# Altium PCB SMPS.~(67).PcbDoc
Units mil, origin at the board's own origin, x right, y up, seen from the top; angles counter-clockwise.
Board outline 3937.01 x 3149.61 mil, 2 copper layers (Top Layer, Bottom Layer); 139 components, 61 nets, 425 pads, 69 vias.
Unrouted connection lines stored in the file: 114.
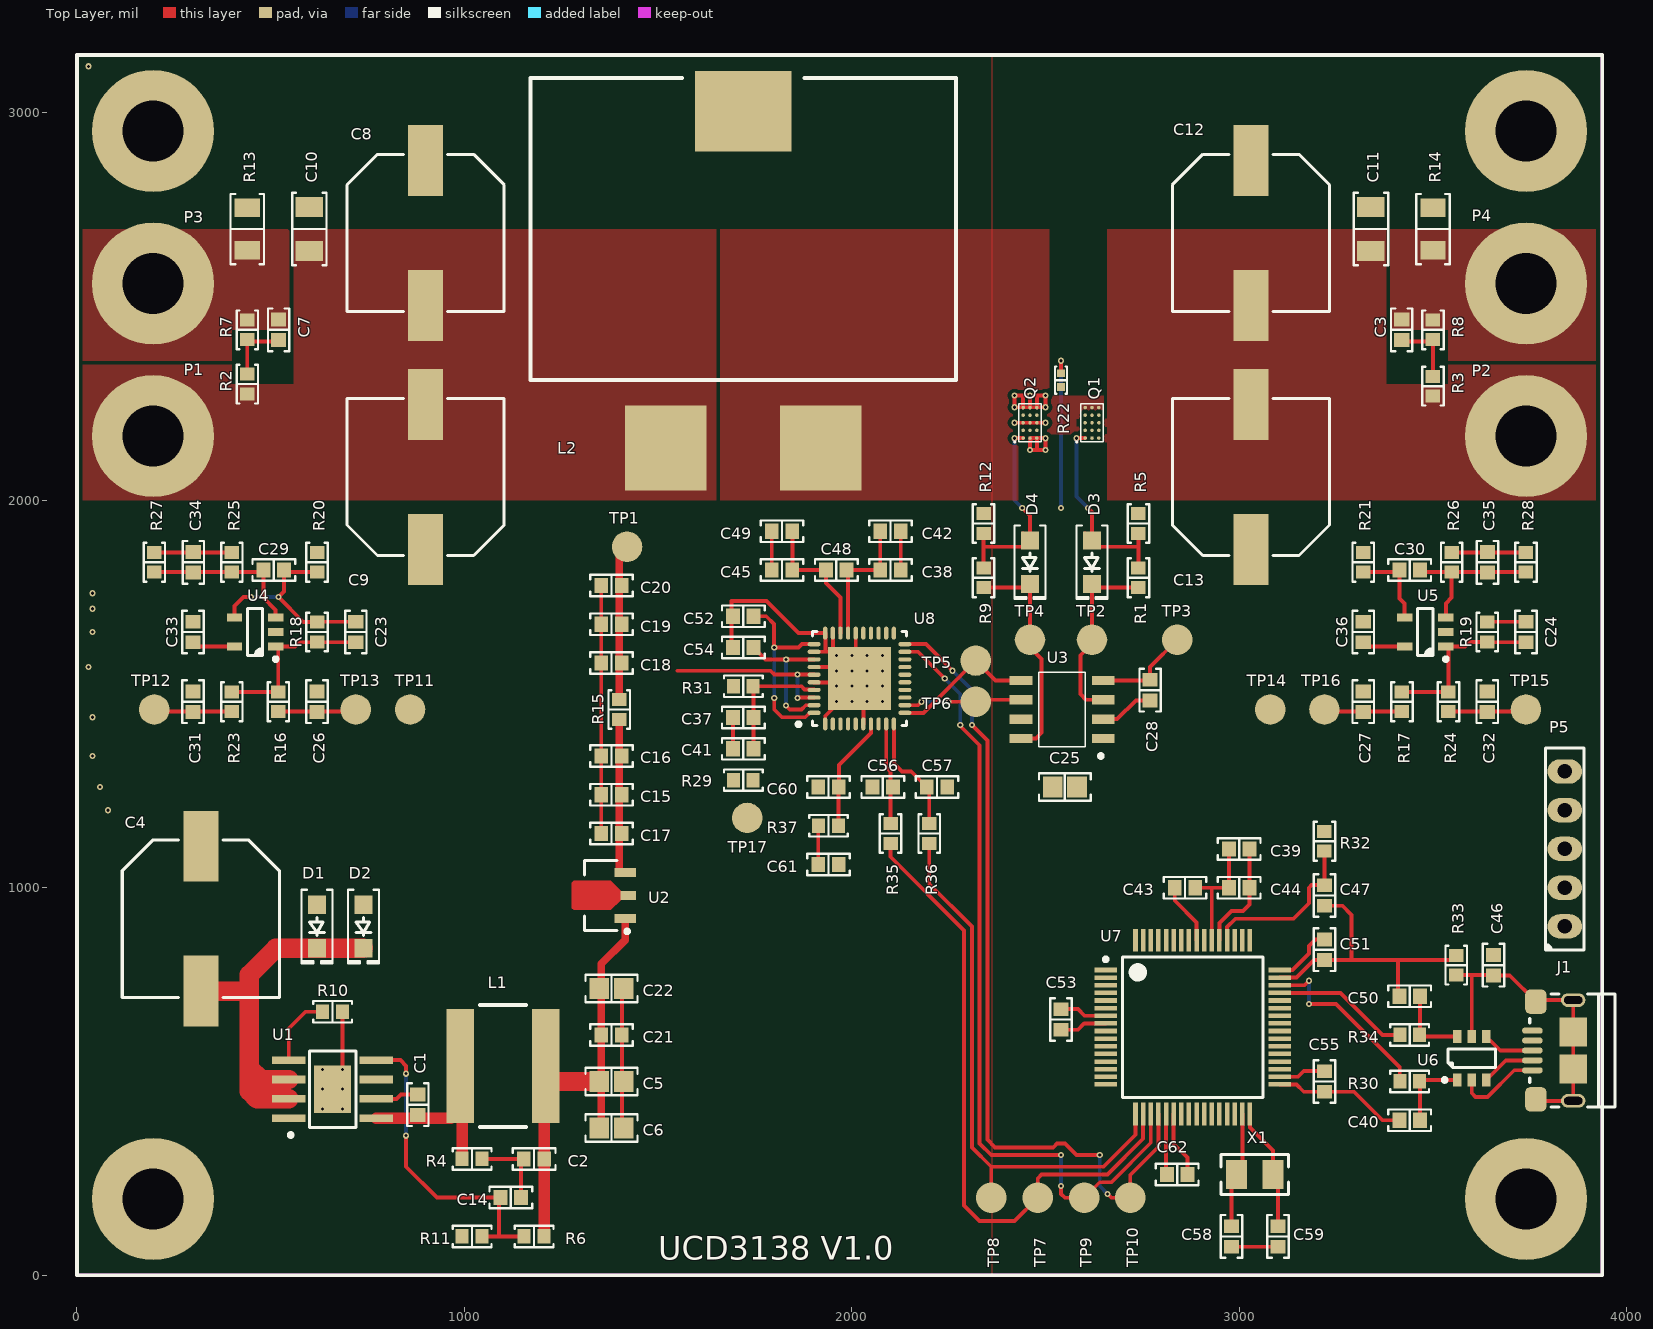
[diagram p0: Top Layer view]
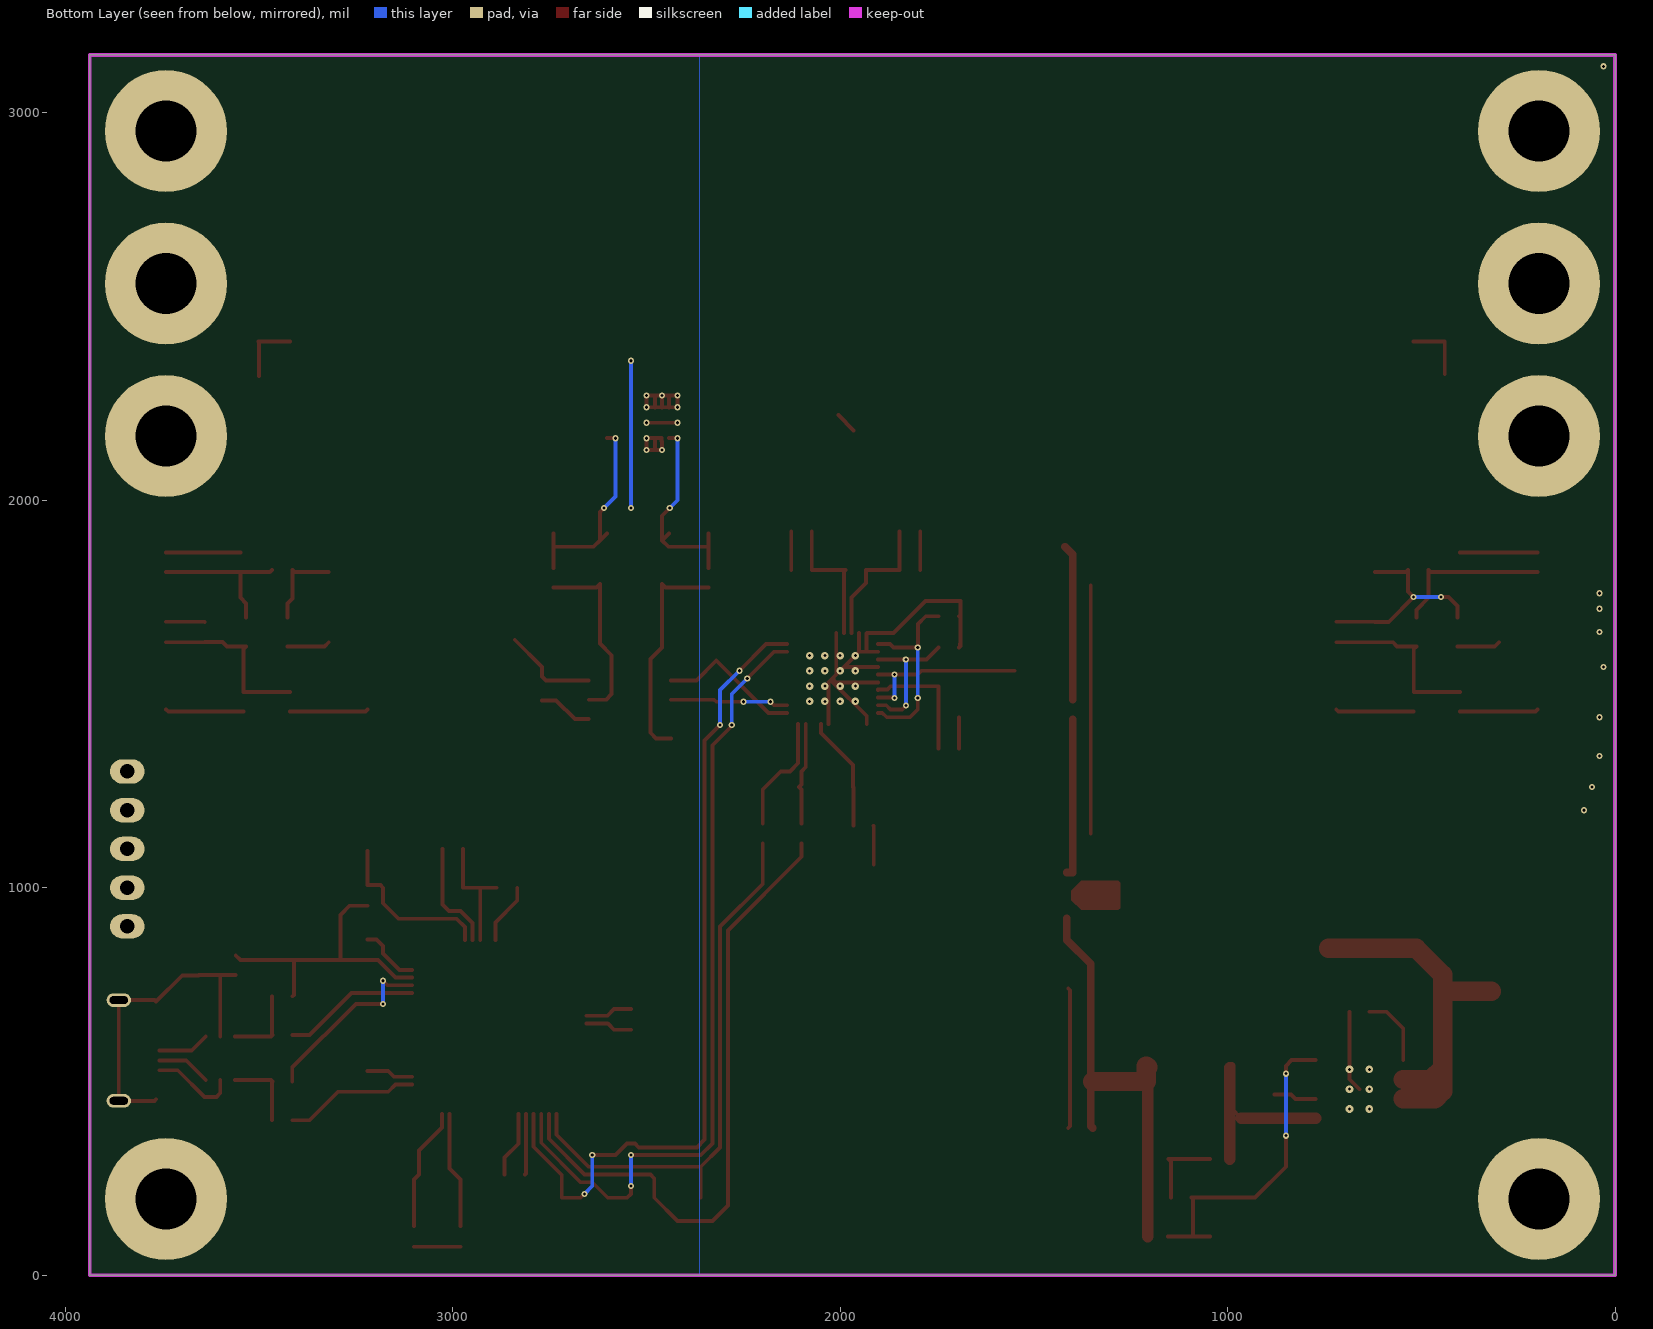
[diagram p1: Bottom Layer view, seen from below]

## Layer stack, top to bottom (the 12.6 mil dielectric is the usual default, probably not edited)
Top Solder: solder mask 0.4, Solder Resist, Dk 3.5
Top Layer: signal copper 1.4
Dielectric 1: dielectric 12.6, FR-4, Dk 4.8
Bottom Layer: signal copper 1.4
Bottom Solder: solder mask 0.4, Solder Resist, Dk 3.5

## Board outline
0,0 0,3149.61 3937.01,3149.61 3937.01,0

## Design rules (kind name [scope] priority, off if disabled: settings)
Clearance [All] p1: gap=10 ignorepadtopadclearanceinfootprint=FALSE except(0: Arc-Hole Track-Hole SMDPad-Hole THPad-Hole Via-Hole Fill-Hole Poly-Hole Region-Hole Text-Hole; 7: SMDPad-SMDPad; 8: Track-SMDPad; 9: Arc-Arc Arc-Track Arc-SMDPad Track-Track; 20: THPad-THPad)
ComponentClearance U1 [InComponent('U1')] p1: gap=20 collisioncheckmode=3 verticalgap=0 showdistances=TRUE
ComponentClearance [All] p2: gap=19.68 collisioncheckmode=3 verticalgap=3.94 showdistances=TRUE
Height [All] p1: minheight=0 maxheight=2000 prefheight=500
HoleSize [All] p1: absolutevalues=TRUE maxlimit=393.7 minlimit=7.87 maxpercent=80.000 minpercent=20.000
MinimumSolderMaskSliver [All] p1: minsoldermaskwidth=1
PlaneClearance [All] p1: clearance=10
PlaneConnect [All] p1: planeconnectstyle=Direct reliefexpansion=20 reliefentries=4 reliefconductorwidth=20 reliefairgap=20
PolygonConnect GND [InNet('GND')] p1: connectstyle=Direct reliefconductorwidth=10 reliefentries=4 polygonreliefangle="90 Angle" airgapwidth=10
PolygonConnect DirectConnect [All] p2: connectstyle=Direct reliefconductorwidth=10 reliefentries=4 polygonreliefangle="90 Angle" airgapwidth=10
RoutingVias [All] p1: holewidth=7.87 width=31.5 viastyle="Through Hole" minholewidth=7.87 minwidth=15.75 maxholewidth=15.75 maxwidth=31.5
SilkToSilkClearance [All] p1: silktosilkclearance=0
SolderMaskExpansion [All] p1: expansion=4
Width [All] p1: maxlimit=500 minlimit=10 preferedwidth=10
23 further rules are at their usual default settings.

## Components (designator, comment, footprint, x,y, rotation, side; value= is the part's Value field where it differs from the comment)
C1 "10nF" C0603 880,440 r90 top
C2 "1nF" C0603 1180,300 r0 top
C3 "10nF" C0603 3419.28,2440 r270 top
C4 "47µF 80V" "CAP ALUM 10.3MM" 320,920 r270 top
C5 "10µF 16V" C0805 1380,500 r0 top
C6 "10µF 16V" C0805 1380,380 r0 top
C7 "10nF" C0603 520.72,2440 r270 top
C8 "47µF 80V" "CAP ALUM 10.3MM" 900,2690 r270 top
C9 "47µF 80V" "CAP ALUM 10.3MM" 900,2060 r90 top
C10 "1µF 80V" C1206 600,2700 r270 top
C11 "1µF 80V" C1206 3340,2700 r270 top
C12 "47µF 80V" "CAP ALUM 10.3MM" 3030,2690 r270 top
C13 "47µF 80V" "CAP ALUM 10.3MM" 3030,2060 r90 top
C14 "47pF" C0603 1120,200.72 r0 top
C15 "10µF" C0603 1380,1240 r180 top
C16 "100nF" C0603 1380,1340 r180 top
C17 "10nF" C0603 1380,1140 r180 top
C18 "10µF" C0603 1380,1580 r180 top
C19 "100nF" C0603 1380,1680 r180 top
C20 "10nF" C0603 1380,1780 r180 top
C21 "100nF 16V" C0603 1380,620 r0 top
C22 "1µF 16V" C0805 1380,740 r0 top
C23 "22pF" C0603 720,1660 r90 top
C24 "22pF" C0603 3740,1660 r270 top
C25 "10µF 16V" C0805 2550,1260 r0 top
C26 "33pF" C0603 620,1480 r270 top
C27 "33pF" C0603 3320,1480 r270 top
C28 "1µF 16V" C0603 2770,1510 r270 top
C29 "22pF" C0603 508.28,1820 r0 top
C30 "22pF" C0603 3440,1820 r180 top
C31 "1µF" C0603 300,1480 r270 top
C32 "1µF" C0603 3640,1480 r270 top
C33 "100nF" C0603 300,1660 r90 top
C34 "22pF" C0603 300.72,1840 r270 top
C35 "22pF" C0603 3640.72,1840 r270 top
C36 "100nF" C0603 3320,1660 r90 top
C37 "4.7µF" C0603 1720,1439.28 r0 top
C38 "4.7µF" C0603 2100,1820 r0 top
C39 "4.7µF" C0603 3000,1100 r180 top
C40 "47pF" C0603 3440,400 r0 top
C41 "10nF" C0603 1720,1358.56 r0 top
C42 "10nF" C0603 2100,1920 r0 top
C43 "100nF" C0603 2860,1000 r180 top
C44 "100nF" C0603 3000,1000 r180 top
C45 "1µF" C0603 1820,1820 r0 top
C46 "10nF" C0603 3656.25,800 r90 top
C47 "100nF" C0603 3220,980 r90 top
C48 "2.2µF" C0603 1960,1820 r0 top
C49 "10nF" C0603 1820,1920 r0 top
C50 "47pF" C0603 3440,720 r0 top
C51 "100nF" C0603 3220,840 r90 top
C52 "1nF" C0603 1720,1700.72 r180 top
C53 "100nF" C0603 2540,660 r90 top
C54 "1nF" C0603 1720,1620 r180 top
C55 "100nF" C0603 3220,500 r90 top
C56 "33pF" C0603 2080,1260 r180 top
C57 "33pF" C0603 2220,1260 r0 top
C58 "26pF" C0603 2980,100 r90 top
C59 "26pF" C0603 3100,100 r90 top
C60 "2.2µF" C0603 1940,1260 r180 top
C61 "1µF" C0603 1940,1060 r0 top
C62 "1µF" C0603 2840,260 r180 top
D1 "DSS120UTR" SOD123F 620,900 r270 top
D2 "DSS120UTR" SOD123F 740,900 r270 top
D3 "DSS120UTR" SOD123F 2620,1840 r270 top
D4 "DSS120UTR" SOD123F 2460,1840 r270 top
J1 "10118192-0001LF" "FCI USB 10118193-0001LF" 3860,580 r270 top
L1 "NR8040T220M" SELF_SMD_8x8 1100,540 r0 top
L2 "PQ2617BHA-220K" SELF_SMD_PQ2617 1720,2700 r0 top
P1 "PTH" HOLE_4#1 196.85,2165.35 r0 top
P2 "PTH" HOLE_4#1 3740.16,2165.35 r0 top
P3 "PTH" HOLE_4#2 196.85,2547.38 r0 top
P4 "PTH" HOLE_4#1 3740.16,2559.06 r0 top
P5 "5x2.54" "SAMTEC SSW-105-03-T-S" 3840,1100.09 r90 top
Q1 "EPC2045" EPC2045 2620,2200 r90 top
Q2 "EPC2045" EPC2045 2460,2200 r90 top
R1 "5R11" R0603 2740,1800 r90 top
R2 "21.5k 0.1%" R0603 440,2300 r90 top
R3 "21.5k 0.1%" R0603 3500,2294.41 r90 top
R4 "249k" R0603 1020,300 r0 top
R5 "10k" R0603 2740,1940 r90 top
R6 "91k" R0603 1180,100 r180 top
R7 "1k 0.1%" R0603 440,2440 r90 top
R8 "1k 0.1%" R0603 3500,2440 r90 top
R9 "5R11" R0603 2340,1800 r90 top
R10 "30.1k" R0603 660,680 r0 top
R11 "10k" R0603 1020,100 r180 top
R12 "10k" R0603 2340,1940 r90 top
R13 "1m 1% 1W 50ppm" R1206 440,2700 r270 top
R14 "1m 1% 1W 50ppm" R1206 3500,2700 r90 top
R15 "1R" R0603 1400,1460 r270 top
R16 "1k" R0603 520,1480 r270 top
R17 "1k" R0603 3420,1480 r90 top
R18 "301k 0.1%" R0603 620,1660 r270 top
R19 "301k 0.1%" R0603 3640,1660 r90 top
R20 "1k 0.1%" R0603 620,1840 r270 top
R21 "1k 0.1%" R0603 3320,1840 r90 top
R22 "10k CTN" "NTC 0402/1005" 2540,2310 r270 top
R23 "1k" R0603 400,1480 r270 top
R24 "1k" R0603 3540,1480 r90 top
R25 "1k 0.1%" R0603 400,1840 r270 top
R26 "1k 0.1%" R0603 3548.28,1840 r90 top
R27 "301k 0.1%" R0603 200,1840 r90 top
R28 "301k 0.1%" R0603 3740,1840 r90 top
R29 "10k" R0603 1720,1277.84 r180 top
R30 "27R" R0603 3440,500 r0 top
R31 "1R" R0603 1720,1520 r0 top
R32 "10k" R0603 3220,1120 r90 top
R33 "1M" R0603 3560,800 r270 top
R34 "27R" R0603 3440,620 r0 top
R35 "100" R0603 2100,1140 r270 top
R36 "100" R0603 2200,1140 r270 top
R37 "2.2k" R0603 1940,1160 r180 top
TP1 "Test Point" "Test Point" 1420,1880 r90 top
TP2 "Test Point" "Test Point" 2620,1640 r0 top
TP3 "Test Point" "Test Point" 2840,1640 r0 top
TP4 "Test Point" "Test Point" 2460,1640 r0 top
TP5 "Test Point" "Test Point" 2320,1586.44 r0 top
TP6 "Test Point" "Test Point" 2320,1480 r0 top
TP7 "Test Point" "Test Point" 2480,200 r0 top
TP8 "Test Point" "Test Point" 2360,200 r0 top
TP9 "Test Point" "Test Point" 2600,200 r0 top
TP10 "Test Point" "Test Point" 2718.86,200 r90 top
TP11 "Test Point" "Test Point" 860,1460 r90 top
TP12 "Test Point" "Test Point" 200,1460 r90 top
TP13 "Test Point" "Test Point" 720,1460 r90 top
TP14 "Test Point" "Test Point" 3080,1460 r90 top
TP15 "Test Point" "Test Point" 3740,1460 r90 top
TP16 "Test Point" "Test Point" 3220,1460 r90 top
TP17 "Test Point" "Test Point" 1730,1180 r90 top
U1 "LM5164" R-PDSO-G8 660,480 r90 top
U2 "AP7381-33Y-13" "ON SEMI SOT-89 H" 1360,980 r180 top
U3 "MIC4605-1YM" SOIC-8 2542.89,1460 r180 top
U4 "LMV793" "TI SOT-23-5 DBV" 460,1660 r180 top
U5 "LMV793" "TI SOT-23-5 DBV" 3480,1660 r180 top
U6 "IP4234CZ6" "VISHAY TSOP-6 MO-193C" 3600,560 r90 top
U7 "ATSAME51J20A" TQFP-64N 2880,640 r0 top
U8 "UCD3138RHAR" S-PVQFN-N40 2020,1540 r90 top
X1 "32.768kHz" "ABRACON ABS07" 3040,260 r0 top

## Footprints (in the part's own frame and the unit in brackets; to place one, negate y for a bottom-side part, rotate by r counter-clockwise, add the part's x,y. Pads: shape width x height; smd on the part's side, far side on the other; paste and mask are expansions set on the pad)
"ABRACON ABS07" [mm] "Crystal, 2-Leads, Body 3.20x1.50mm, IPC Medium Density"
  rect 1.4x1.9 smd: 1(-1.2,0) 2(1.2,0)
  silkscreen extent -2.2,-1.3 2.2,1.3, body extent -1.62,-0.77 1.63,0.78, height 0.9
C0603 [mm] "Chip Capacitor, 2-Leads, Body 1.60x0.80mm, IPC Medium Density"
  rect 0.9x1 smd: 1(-0.675,0) 2(0.675,0)
  silkscreen extent -1.4,-0.7 1.4,0.7, body extent -0.8,-0.41 0.8,0.41, height 0.82
C0805 [mm] "Chip Capacitor, 2-Leads, Body 2.00x1.20mm, IPC Medium Density"
  rect 1.3x1.4 smd: 1(-0.8,0) 2(0.8,0)
  silkscreen extent -1.7,-0.9 1.7,0.9, body extent -1,-0.64 1,0.64, height 1.26
C1206 [mm] "Chip Capacitor, 2-Leads, Body 3.25x1.60mm, IPC Medium Density"
  rect 1.3x1.8 smd: 1(-1.45,0) 2(1.45,0)
  silkscreen extent -2.37,-1.12 2.37,1.12, body extent -1.6,-0.81 1.6,0.81, height 1.62
"CAP ALUM 10.3MM" [mm] "Aluminum Electrolytic Capacitor, Body 10.30x10.30x10.50mm, IPC Low Density"
  rect 4.65x2.3 smd: 1(-4.75,0) 2(4.75,0)
  silkscreen extent -5.15,-5.15 5.15,5.15, body extent -5.8,-5.15 5.8,5.15, height 10.5
EPC2045 [mm] "EPC2045 GaNFet"
  round 0.23 smd: 1(-1,0.45) 2(-1,-0.45) 2(-1,0) 2(0,0) 2(0,0.45) 2(0,-0.45) 2(1,-0.45) 2(1,0) 2(1,0.45) 3(-0.5,-0.45) 3(-0.5,0) 3(-0.5,0.45) 3(0.5,-0.45) 3(0.5,0) 3(0.5,0.45)
  silkscreen extent -1.3,-0.75 1.25,1.05, body extent -1.25,-0.75 1.25,0.75, height 0.68
"FCI USB 10118193-0001LF" [mm] "USB 2.0 Type B Micro"
  oval 0.4x1.35 smd: 1(1.3,-2.625) 2(0.65,-2.625) 3(0,-2.625) 4(-0.65,-2.625) 5(-1.3,-2.625)
  oval 0.9x1.6 hole 0.5 slot 1.2 at 90 deg: S(-3.3,0.05) S(3.3,0.05)
  rrect50% 1.6x1.4 smd: S(-3.2,-2.4) S(3.2,-2.4)
  rect 1.9x1.8 smd: S(-1.2,0.05) S(1.2,0.05)
  silkscreen extent -3.7,-2.8 3.7,2.8, body extent -3.93,-2.9 3.93,2.76, height 2.78
HOLE_4#1 [mm] "Hole for M4 screw"
  round 8 hole 4: 1(0,0)
HOLE_4#2 [mm] "Hole for M4 screw"
  round 8 hole 4: 1(0,0.297)
"NTC 0402/1005" [mm] "Chip Thermistor, 2-Leads, Body 1.00x0.50mm, IPC Medium Density"
  rect 0.5x0.55 smd: 1(-0.45,0) 2(0.45,0)
  silkscreen extent -0.9,-0.4 0.9,0.4, body extent -0.5,-0.26 0.5,0.26, height 0.52
"ON SEMI SOT-89 H" [mm] "SOT89, 3-Leads, Body 4.50x2.50mm, Pitch 1.50mm, Lead Span 3.3mm, IPC Medium Density"
  rect 1.4x0.6 smd: 1(-1.4,1.5) 3(-1.4,-1.5)
  rect 1x0.6 smd: 2(-1.6,0)
  Top Layer region: -1.1,0.3 -0.45,0.95 1.975,0.95 2.1,0.825 2.1,-0.825 1.975,-0.95 -0.45,-0.95 -1.1,-0.3
  silkscreen extent -1.65,-2.3 1.25,2.47, body extent -2.05,-2.25 2.1,2.25, height 1.5
R0603 [mm] "Chip Resistor, 2-Leads, Body 1.60x0.80mm, IPC Medium Density"
  rect 0.85x0.95 smd: 1(-0.65,0) 2(0.65,0)
  silkscreen extent -1.27,-0.7 1.27,0.7, body extent -0.8,-0.4 0.8,0.4, height 0.45
R1206 [mm] "Chip Resistor, 2-Leads, Body 3.13x1.55mm, IPC Medium Density"
  rect 1.2x1.65 smd: 1(-1.4,0) 2(1.4,0)
  silkscreen extent -2.3,-1.1 2.3,1.1, body extent -1.57,-0.8 1.62,0.8, height 0.6
R-PDSO-G8 [mm] "SOIC, 8-Leads, Body 4,90x3,90mm, Pitch 1,27mm, Thermal Pad 3,10x2,40mm, IPC Medium Density"
  rect 0.5x2.2 smd: 1(-1.905,2.875) 2(-0.635,2.875) 3(0.635,2.875) 4(1.905,2.875) 5(1.905,-2.875) 6(0.635,-2.875) 7(-0.635,-2.875) 8(-1.905,-2.875)
  rect 3.1x2.4 smd paste+0: 9(0,0)
  silkscreen extent -3.12,-1.52 2.5,2.87, body extent -2.5,-2 2.5,2, height 1.7
S-PVQFN-N40 [mm] "VQFN, 40-Leads, Body 6,00x6,00mm, Pitch 0,50mm, Thermal Pad 4,92x4,92mm, IPC Medium Density"
  oval 0.85x0.28 smd: 1(-2.975,2.25) 2(-2.975,1.75) 3(-2.975,1.25) 4(-2.975,0.75) 5(-2.975,0.25) 6(-2.975,-0.25) 7(-2.975,-0.75) 8(-2.975,-1.25) 9(-2.975,-1.75) 10(-2.975,-2.25) 21(2.975,-2.25) 22(2.975,-1.75) 23(2.975,-1.25) 24(2.975,-0.75) 25(2.975,-0.25) 26(2.975,0.25) 27(2.975,0.75) 28(2.975,1.25) 29(2.975,1.75) 30(2.975,2.25)
  oval 0.28x0.85 smd: 11(-2.25,-2.975) 12(-1.75,-2.975) 13(-1.25,-2.975) 14(-0.75,-2.975) 15(-0.25,-2.975) 16(0.25,-2.975) 17(0.75,-2.975) 18(1.25,-2.975) 19(1.75,-2.975) 20(2.25,-2.975) 31(2.25,2.975) 32(1.75,2.975) 33(1.25,2.975) 34(0.75,2.975) 35(0.25,2.975) 36(-0.25,2.975) 37(-0.75,2.975) 38(-1.25,2.975) 39(-1.75,2.975) 40(-2.25,2.975)
  rect 4.15x4.15 smd paste-2.075: 41(0,0)
  silkscreen extent -3.12,-3.08 3.08,4.12, body extent -3.08,-3.08 3.08,3.08, height 1
"SAMTEC SSW-105-03-T-S" [mm]
  oval 1.6x2.25 hole 0.95: 1(-5.08,0) 2(-2.54,0) 3(0,0) 4(2.54,0) 5(5.08,0)
  silkscreen extent -6.61,-1.27 6.61,1.27, body extent -6.6,-1.21 6.6,1.21, height 8.51
SELF_SMD_8x8 [mm] "Self SMD 8x8mm"
  rect 1.8x7.5 smd: 1(-2.8,0) 2(2.8,0)
  silkscreen extent -1.5,-4 1.5,4, body extent -4,-4 4,4, height 3
SELF_SMD_PQ2617 [mil] "Bourns shielded power inductor PQ2617"
  rect 210x220 smd: 1(-200,-565) 2(200,-565)
  rect 250x208 smd: 3(0,304)
  silkscreen extent -549,-390 549,390, body extent -549,-433 549,433, height 748
SOD123F [mm] "SODFL, 2-Leads, Body 1.60x3.50mm, IPC Medium Density"
  rect 1.2x1.2 smd: 1(-1.43,0) 2(1.43,0)
  silkscreen extent -2.41,-1.02 2.41,1.02, body extent -1.75,-0.8 1.75,0.8, height 1.1
SOIC-8 [mm] "8-Pin Plastic Narrow Body Small Outline Integrated Circuit 1.27 mm Pitch, IPC Medium Density"
  rect 1.5x0.6 smd: 1(-2.7,1.905) 2(-2.7,0.635) 3(-2.7,-0.635) 4(-2.7,-1.905) 5(2.7,-1.905) 6(2.7,-0.635) 7(2.7,0.635) 8(2.7,1.905)
  silkscreen extent -2.67,-2.45 1.52,3.17, body extent -1.95,-2.45 1.95,2.45, height 1.76
"Test Point" [mm] "Test Point"
  round 2 smd: 1(0,0)
"TI SOT-23-5 DBV" [mm] "SOT23, 5-Leads, Body 2.90x2.80mm, Pitch 0.95mm, IPC Medium Density"
  rect 1x0.55 smd: 1(-1.35,0.95) 2(-1.35,0) 3(-1.35,-0.95) 4(1.35,-0.95) 5(1.35,0.95)
  silkscreen extent -1.48,-1.55 0.5,1.9, body extent -1.44,-1.43 1.39,1.48, height 1.5
TQFP-64N [mm] "TSQFP, 64-Leads, Body 10,00x10,00mm, Pitch 0,50mm, IPC Medium Density"
  rect 1.5x0.3 smd: 1(-5.7,3.75) 2(-5.7,3.25) 3(-5.7,2.75) 4(-5.7,2.25) 5(-5.7,1.75) 6(-5.7,1.25) 7(-5.7,0.75) 8(-5.7,0.25) 9(-5.7,-0.25) 10(-5.7,-0.75) 11(-5.7,-1.25) 12(-5.7,-1.75) 13(-5.7,-2.25) 14(-5.7,-2.75) 15(-5.7,-3.25) 16(-5.7,-3.75) 33(5.7,-3.75) 34(5.7,-3.25) 35(5.7,-2.75) 36(5.7,-2.25) 37(5.7,-1.75) 38(5.7,-1.25) 39(5.7,-0.75) 40(5.7,-0.25) 41(5.7,0.25) 42(5.7,0.75) 43(5.7,1.25) 44(5.7,1.75) 45(5.7,2.25) 46(5.7,2.75) 47(5.7,3.25) 48(5.7,3.75)
  rect 0.3x1.5 smd: 17(-3.75,-5.7) 18(-3.25,-5.7) 19(-2.75,-5.7) 20(-2.25,-5.7) 21(-1.75,-5.7) 22(-1.25,-5.7) 23(-0.75,-5.7) 24(-0.25,-5.7) 25(0.25,-5.7) 26(0.75,-5.7) 27(1.25,-5.7) 28(1.75,-5.7) 29(2.25,-5.7) 30(2.75,-5.7) 31(3.25,-5.7) 32(3.75,-5.7) 49(3.75,5.7) 50(3.25,5.7) 51(2.75,5.7) 52(2.25,5.7) 53(1.75,5.7) 54(1.25,5.7) 55(0.75,5.7) 56(0.25,5.7) 57(-0.25,5.7) 58(-0.75,5.7) 59(-1.25,5.7) 60(-1.75,5.7) 61(-2.25,5.7) 62(-2.75,5.7) 63(-3.25,5.7) 64(-3.75,5.7)
  silkscreen extent -5.82,-4.6 4.6,4.6, body extent -5,-5 5,5, height 1.2
"VISHAY TSOP-6 MO-193C" [mm] "SOT23, 6-Leads, Body 3.03x2.84mm, Pitch 0.95mm, IPC Medium Density"
  rect 0.85x0.55 smd: 1(-1.425,0.95) 2(-1.425,0) 3(-1.425,-0.95) 4(1.425,-0.95) 5(1.425,0) 6(1.425,0.95)
  silkscreen extent -1.55,-1.55 0.6,1.9, body extent -1.44,-1.52 1.44,1.53, height 1.45

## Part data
C1 C2 C3 C4 C5 C6 C7 C8 C9 C10 C11 C12 C13 C14 C15 C16 C17 C18 C19 C20 C21 C22 C23 C24 C25 C26 C27 C28 C29 C30 C31 C32 C33 C34 C35 C36 C37 C38 C39 C40 C41 C42 C43 C44 C45 C46 C47 C48 C49 C50 C51 C52 C53 C54 C55 C56 C57 C58 C59 C60 C61 C62: library part Cap, "Capacitor"
D1 D2 D3 D4: library part "D Schottky", "Schottky Diode"
J1: library part 1-353576-1, "USB 1.1, Right Angle, SMT, A Type, Receptacle, 4 Position, White"
L1 L2: library part "Inductor Iron", "Magnetic-Core Inductor"
P1 P2 P3 P4: "Plated Trough Hole for screew"
P5: library part "Header 5", "Header, 5-Pin"
Q1 Q2: library part MOSFET_N
R1 R2 R3 R4 R5 R6 R7 R8 R9 R10 R11 R12 R13 R14 R15 R16 R17 R18 R19 R20 R21 R23 R24 R25 R26 R27 R28 R29 R30 R31 R32 R33 R34 R35 R36 R37: library part Res2, "Resistor"
R22: library part "Res Varistor", "Varistor (Voltage-Sensitive Resistor)"
U1: "100-V Input, 1-A synchronous buck DC/DC converter with ultra-low IQ"
U2: library part "Volt Reg", "Voltage Regulator"
U3: "85V Half-Bridge MOSFET Driver with Adaptive Dead Time  and Shoot-Through Protection"
U4 U5: library part "AOP - 1"
U6: "Single USB 2.0 ESD protection to IEC 61000-4-2 level 4"
U8: "Highly Integrated Digital Controller for Isolated Power with 3 Feedback Loops and 8 DPWM Outputs, 40pins"
X1: library part XTAL, "Crystal Oscillator"

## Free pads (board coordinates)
  round 314.96 hole 157.48: 1(196.85,196.85) 1(196.85,2952.76) 1(3740.16,196.85) 1(3740.16,2952.76)

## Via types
v1: diameter 15.75, hole 7.87, Top Layer to Bottom Layer, 47 vias
v2: diameter 19.68, hole 7.87, Top Layer to Bottom Layer, 22 vias

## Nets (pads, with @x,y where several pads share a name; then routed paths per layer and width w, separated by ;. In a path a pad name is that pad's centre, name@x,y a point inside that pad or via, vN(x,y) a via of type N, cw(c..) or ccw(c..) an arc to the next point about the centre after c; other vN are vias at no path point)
+3.3V: C15.1 C16.1 C17.1 C38.1 C42.1 C43.2 C48.2 C51.2 C53.1 C55.2 C62.2 P5.1 R15.2 R22.2 R31.1 R32.2 U2.3 U7.8 U7.21 U7.34 U7.48 U7.56 U8.27 | length 1481.3
  Top Layer w10: U8.27 1990.47,1816.1 C48.2 C38.1 C42.1 ; C53.1 2583.43,633.43 2599.84,649.84 U7.8 ; U7.21 2811.1,262.32 C62.2 ; C43.2 2833.43,966.57 2889.84,910.16 U7.56 ; U7.34 3152.05,512.05 3166.57,526.57 C55.2 ; U7.48 3137.64,787.64 3180,830 3180,850 3196.57,866.57 C51.2
  Top Layer w20: R15.2 1400,1039.06 U2.3
+3.3Vana: C18.1 C19.1 C20.1 C33.1 C36.1 R15.1 TP1.1 U4.5 U5.5 | length 625.4
  Top Layer w10: C33.1 310.83,1622.6 U4.5 ; C36.1 3330.83,1622.6 U5.5
  Top Layer w20: R15.1 1400,1860 TP1.1
+12V: C2.2 C5.1 C6.1 C21.1 C22.1 C25.2 L1.2 R6.1 U2.1 U3.1 | length 1188.3
  Top Layer w20: C6.1 1353.43,384.92 C21.1 1353.43,803.43 1415.12,865.12 U2.1
  Top Layer w30: R6.1@1206.57,100 L1.2@1206.57,536.34
  Top Layer w50: L1.2@1206.57,536.34 L1.2 1210.24,500 C5.1
+Vbus: C8.2 C9.2 C10.2 D1.1 L2.1 P1.1 R2.1
+Vcells: C11.2 C12.2 C13.2 D2.1 P2.1 Q1.3 R3.1
ALERT: TP9.1 U7.19 U8.19 | length 2059.6
  Top Layer w10: U8.19 2171.1,1608.9 v1(2240,1540) ; v1(2280,1420) 2280,1417.65 2330,1367.65 2330,340 2360,310 v1(2540,310) ; v1(2540,230) 2540,210 2550,200 TP9.1 2640,240 2670,240 2771.73,341.73 U7.19
  Bottom Layer w10: v1(2240,1540) 2280,1500 v1(2280,1420) ; v1(2540,230) v1(2540,310)
Ccells: C28.1 L2.2 Q1.2 Q2.3 R5.2 TP3.1 U3.4 | length 304.4
  Top Layer w10: L2.2@1965.32,2180.32 L2.2@2004.69,2219.69 ; U3.4 2759.56,1535 2770,1545.44 2770,1570 TP3.1
CTRL: TP10.1 U7.20 U8.20 | length 2130.3
  Top Layer w10: U8.20 2191.42,1628.58 v1(2260,1560) ; v1(2310,1420) 2350,1380 2350,350 2370,330 2520,330 2530,340 2550,340 2580,310 v1(2640,310) ; v1(2660,210) 2670,200 TP10.1 2718.86,258.86 2791.42,331.42 U7.20
  Bottom Layer w10: v1(2260,1560) 2310,1510 v1(2310,1420) ; v1(2640,310) 2640,230 v1(2660,210)
DPWM0A: TP5.1 U3.5 U8.11 | length 376.7
  Top Layer w10: U8.11 2184.98,1451.42 TP5.1 2371.44,1535 U3.5
DPWM0B: TP6.1 U3.6 U8.12 | length 305.2
  Top Layer w10: U8.12 2171.1,1471.1 v1(2180,1480) ; v1(2250,1480) TP6.1 2325,1485 U3.6
  Bottom Layer w10: v1(2180,1480) v1(2250,1480)
GND: C4.1 C5.2 C6.2 C8.1 C9.1 C10.1 C11.1 C12.1 C13.1 C15.2 C16.2 C17.2 C18.2 C19.2 C20.2 C21.2 C22.2 C25.1 C26.1 C27.1 C31.1 C32.1 C33.2 C34.1 C35.1 C36.2 C37.1 C38.2 C39.2 C40.1 C41.1 C42.2 C43.1 C44.2 C45.1 C46.2 C47.1 C49.1 C50.1 C51.1 C52.2 C53.2 C54.2 C55.1 C56.2 C57.2 C58.1 C59.1 C60.2 C61.2 C62.1 J1.5 P5.5 pad.1 Q2.2 R10.2 R11.2 R12.2 R13.1 R14.2 R25.1 R26.2 R27.2 R28.2 R29.2 R33.1 U1.1 U1.9 U2.2 U3.7 U4.2 U5.2 U7.7 U7.22 U7.33 U7.47 U7.54 U8.1 U8.6 U8.26 U8.29 U8.30 U8.32 U8.34 U8.36 U8.41 | length 5550.4
  Top Layer w10: R27.2 R25.1 ; U1.9 685.59,505.59 R10.2 ; C17.2 C15.2 C16.2 C18.2 C19.2 C20.2 ; C6.2 1406.57,384.92 C21.2 1406.57,735.08 C22.2 ; C41.1 C37.1 ; C54.2 C54.2@1690.47,1622.95 ; C52.2 C52.2@1690,1697.29 ; C45.1 C49.1 ; U8.36 2010.16,1530.16 U8.41 ; U8.34 U8.41@1990.47,1569.53 ; U8.32 1930,1608.9 ; U8.1 1931.42,1442.56 2020,1531.14 U8.41 ; U8.29 U8.41@1951.1,1608.9 ; U8.26 U8.41@2010.16,1549.84 ; U8.6 2029.84,1530.16 U8.41 ; C38.2 C42.2 ; v1(2420,2200) 2460,2200 v1(2500,2200) ; Q2.2@2442.28,2239.37 Q2.2@2442.28,2240 ; Q2.2@2460,2239.37 Q2.2@2460,2240 ; Q2.2@2477.71,2239.37 Q2.2@2477.71,2240 ; C53.2 2583.43,686.57 2600.47,669.53 U7.7 ; U7.22 2830.79,339.21 2866.57,303.43 C62.1 ; C43.1 2930,1000 ; U7.54 2929.21,999.21 2930,1000 ; C39.2 C44.2 2930,1000 ; C58.1 C59.1 ; U7.33 3147.64,492.36 3166.57,473.43 C55.1 3296.57,473.43 3370,400 C40.1 ; U7.47 3147.95,767.95 3193.43,813.43 C51.1 3290,813.43 ; C47.1 3266.57,953.43 3290,930 3290,813.43 ; C50.1 3410,723.43 3410,813.43 ; R26.2 R28.2 ; R33.1 3547.83,813.43 3410,813.43 ; C54.2@1690,1630 1690,1623.43 C54.2@1690.47,1622.95 ; C54.2@1690,1630 1690.47,1629.53 C54.2@1690.47,1622.95 ; C54.2@1690,1630 C52.2@1690,1697.29 ; C52.2@1690,1697.29 1690,1740 1780,1740 1862.87,1657.13 U8.30 1932.61,1655.94 1932.61,1611.5 1930,1608.9 ; 1930,1608.9 U8.41@1951.1,1608.9 ; U8.41@1951.1,1608.9 v2(1960.94,1599.06) U8.41@1990.47,1569.53 ; U8.41@1990.47,1569.53 v2(2000.31,1559.69) U8.41@2010.16,1549.84 ; U8.41@2010.16,1549.84 U8.41 ; 2440,2270 v1(2460,2270) ; 2440,2270 v1(2420,2270) v1(2420,2240) Q2.2@2442.28,2240 ; 2440,2270 2442.28,2267.72 Q2.2@2442.28,2240 ; Q2.2@2442.28,2240 Q2.2@2460,2240 ; Q2.2@2460,2240 v1(2460,2270) ; Q2.2@2460,2240 Q2.2@2477.71,2240 ; v1(2460,2270) 2480,2270 ; Q2.2@2477.71,2160.63 2461.28,2160.63 2461.28,2152.76 2460,2151.48 v1(2460,2130) 2480,2130 ; Q2.2@2477.71,2160.63 2499.37,2160.63 v1(2500,2160) v1(2500,2130) 2480,2130 ; Q2.2@2477.71,2160.63 2477.71,2132.29 2480,2130 ; Q2.2@2477.71,2240 v1(2500,2240) v1(2500,2270) 2480,2270 ; Q2.2@2477.71,2240 2477.71,2267.71 2480,2270 ; 3290,813.43 3410,813.43
  other v1: 80,1200 60,1260 40,1340 40,1440 30,1570 40,1660 40,1720 40,1760 30,3120
  other v2: 634.41,428.82 685.59,428.82 634.41,480 685.59,480 634.41,531.18 685.59,531.18 1960.94,1480.94 2000.31,1480.94 2039.69,1480.94 2079.06,1480.94 1960.94,1520.31 2000.31,1520.31 2039.69,1520.31 2079.06,1520.31 1960.94,1559.69 2039.69,1559.69 2079.06,1559.69 2000.31,1599.06 2039.69,1599.06 2079.06,1599.06
Hcells: D3.2 R1.1 TP2.1 U3.3 | length 485.4
  Top Layer w10: U3.3 2605,1485 2590,1500 2590,1600 2620,1630 TP2.1 D3.2 2629.29,1774.41 R1.1
Ibus_peak: C26.2 R16.2 TP13.1 U8.5 | length 202.3
  Top Layer w10: R16.2 714.41,1454.41 TP13.1
Ibus_sense: C31.2 R23.2 TP12.1 U8.4 | length 202.3
  Top Layer w10: TP12.1 205.59,1454.41 R23.2
Icells_peak: C27.2 R17.1 TP16.1 U8.2 | length 202.3
  Top Layer w10: TP16.1 3225.59,1454.41 R17.1
Icells_sense: C32.2 R24.1 TP15.1 U8.35 U8.38 | length 662.4
  Top Layer w10: 1550,1560 1790,1560 1800.16,1549.84 v1(1860,1549.84) U8.35 ; v1(1860,1490) 1860.79,1490.79 U8.38 ; R24.1 3734.41,1454.41 TP15.1
  Bottom Layer w10: v1(1860,1490) v1(1860,1549.84)
Lcells: D4.2 R9.1 TP4.1 U3.8 | length 579.6
  Top Layer w10: R9.1 2450.71,1774.41 D4.2 TP4.1 2460,1620 2490,1590 2490,1400 2475,1385 U3.8
NetC1_1: C1.1 L1.1 R4.1 U1.8 | length 579
  Top Layer w10: L1.1@965,405 989.76,429.76 L1.1
  Top Layer w20: L1.1 L1.1@994.41,535.35
  Top Layer w30: U1.8 L1.1@965,405 ; R4.1 L1.1@994.41,535.35
NetC1_2: C1.2 U1.7 | length 111.6
  Top Layer w10: U1.7 825,455 836.57,466.57 C1.2
NetC2_1: C2.1 C14.2 R4.2 | length 210
  Top Layer w10: R4.2 C2.1 1146.57,293.15 C14.2
NetC4_2: C4.2 D1.2 D2.2 U1.2 U1.3 | length 972.8
  Top Layer w50: C4.2 445,732.99 ; U1.2 465,455 445,475 445,535 ; U1.3 475,505 445,535 ; D2.2 D1.2 513.7,843.7 445,775 445,732.99 ; 445,535 445,732.99
NetC14_1: C14.1 R6.2 R11.1 U1.5 | length 830.2
  Top Layer w10: U1.5 835,555 850,540 v1(850,520) ; v1(850,360) 850,280 929.28,200.72 C14.1 1090,197.29 1090,100 ; R11.1 1090,100 ; R6.2 1090,100
  Bottom Layer w10: v1(850,360) v1(850,520)
NetC23_1: C23.1 R16.1 R18.2 R23.1 U4.1 | length 451.2
  Top Layer w10: R23.1 R16.1 520,1615.75 U4.1 562.6,1622.6 573.43,1633.43 C23.1
NetC23_2: C23.2 C29.2 R18.1 R20.2 U4.4 | length 542.9
  Top Layer w10: U4.4 406.85,1726.85 430,1750 v1(450,1750) ; R20.2 540.44,1814.41 C29.2 534.85,1764.85 v1(520,1750) 584.41,1685.59 R18.1 620.98,1686.57 C23.2
  Bottom Layer w10: v1(450,1750) v1(520,1750)
NetC24_1: C24.1 C30.2 R19.2 R21.1 U5.4 | length 324.3
  Top Layer w10: R21.1 3407.83,1814.41 C30.2 3413.43,1746.57 3426.85,1733.15 U5.4 ; R19.2 3640.98,1686.57 C24.1
NetC24_2: C24.2 R17.2 R19.1 R24.2 U5.1 | length 452
  Top Layer w10: R17.2 R24.2 3540,1615.75 U5.1 3582.6,1622.6 3594.41,1634.41 R19.1 3640.98,1633.43 C24.2
NetC28_2: C28.2 U3.2 | length 140.9
  Top Layer w10: U3.2 2685,1435 2733.43,1483.43 C28.2
NetC29_1: C29.1 C34.2 R25.2 R27.1 U4.3 | length 419.6
  Top Layer w10: R27.1 476.11,1814.41 C29.1 481.7,1748.3 513.15,1716.85 U4.3
NetC30_1: C30.1 C35.2 R26.1 R28.1 U5.3 | length 399
  Top Layer w10: C30.1 3472.17,1814.41 R26.1 ; U5.3 3533.15,1734.02 3548.28,1749.14 R26.1 ; R28.1 R26.1
NetC37_2: C37.2 C41.2 R31.2 U8.37 | length 323.1
  Top Layer w10: C41.2 C37.2 1746.57,1519.02 R31.2 1870,1520 1878.35,1511.65 1894.52,1511.65 1895,1511.16 1902.19,1511.16 U8.37
NetC39_1: C39.1 C44.1 U7.53 | length 285.3
  Top Layer w10: U7.53 2948.9,908.9 2980,940 3010,940 3026.57,956.57 C44.1 C39.1
NetC40_2: C40.2 R30.2 U6.1 | length 199.6
  Top Layer w10: R30.2 R30.2@3466.57,500.98 ; C40.2 R30.2@3466.57,500.98 ; U6.1 3469.49,503.9 R30.2@3466.57,500.98
NetC45_2: C45.2 C48.1 C49.2 U8.28 | length 365.2
  Top Layer w10: C49.2 C45.2 C48.1 1933.43,1786.57 1970.79,1749.21 U8.28
NetC46_1: C46.1 J1.S R33.2 U6.5 | length 848.2
  Top Layer w10: R33.2 3600,774.41 ; U6.5 3600,774.41 ; J1.S@3765.51,454.02 3769.45,450.08 3861.97,450.08 3861.97,532.76 3861.97,627.24 3861.97,709.92 3769.45,709.92 3765.51,705.98 3698.07,773.43 C46.1 3655.27,774.41 3600,774.41
NetC50_2: C50.2 R34.2 U6.6 | length 199.6
  Top Layer w10: R34.2 R34.2@3466.57,619.02 ; C50.2 R34.2@3466.57,619.02 ; U6.6 3469.49,616.1 R34.2@3466.57,619.02
NetC56_1: C56.1 R35.1 U8.9 | length 267.3
  Top Layer w10: U8.9 2088.9,1311.1 2100,1300 2100,1266.57 C56.1 2100,1253.43 R35.1
NetC57_1: C57.1 R36.1 U8.10 | length 308.9
  Top Layer w10: U8.10 2108.58,1321.42 2130,1300 2153.43,1300 C57.1 2200,1253.43 R36.1
NetC58_2: C58.2 U7.31 X1.1 | length 300.6
  Top Layer w10: C58.2 2980,247.24 X1.1 3007.95,275.2 U7.31
NetC59_2: C59.2 U7.32 X1.2 | length 319
  Top Layer w10: U7.32 3027.64,381.42 3087.24,321.81 X1.2 3100,247.24 C59.2
NetC60_1: C60.1 R37.1 U8.7 | length 297.6
  Top Layer w10: R37.1 1965.59,1259.02 C60.1 1966.57,1316.57 2049.53,1399.53 U8.7
NetD3_1: D3.1 Q1.1 R1.2 R5.1 | length 543.4
  Top Layer w10: v1(2580,2160) 2580.63,2160.63 Q1.1 ; D3.1@2602.28,1914.02 D3.1 ; v1(2610,1980) 2620,1970 D3.1 ; R1.2 2740,1880 ; R5.1 2740,1880 ; D3.1 2636.3,1880 2740,1880
  Bottom Layer w10: v1(2580,2160) 2580,2010 v1(2610,1980)
NetD4_1: D4.1 Q2.1 R9.2 R12.1 | length 543.4
  Top Layer w10: R9.2 2340,1880 ; R12.1 2340,1880 ; v1(2420,2160) 2420.63,2160.63 Q2.1 ; v1(2440,1980) 2460,1960 D4.1 ; D4.1@2442.28,1914.02 D4.1 ; 2340,1880 2443.7,1880 D4.1
  Bottom Layer w10: v1(2420,2160) 2420,2000 v1(2440,1980)
NetJ1_1: J1.1 U6.2 | length 223.2
  Top Layer w10: U6.2 3600,470 3610,460 3640.87,460 3709.68,528.82 J1.1
NetJ1_2: J1.2 U6.3 | length 140.2
  Top Layer w10: U6.3 3687.91,554.41 J1.2
NetJ1_3: J1.3 U6.4 | length 134.2
  Top Layer w10: U6.4 3673.5,580 J1.3
NetR10_1: R10.1 U1.4 | length 187.3
  Top Layer w10: U1.4 546.81,636.81 590,680 R10.1
R\S\T\: C47.2 P5.4 R32.1 U7.52 | length 441.6
  Top Layer w10: U7.52 2968.58,898.58 2990,920 3140,920 3180,960 3180,1000 3186.57,1006.57 C47.2 R32.1
Rbus: C7.1 P3.1 R7.2 R13.2 R20.1
Rcells: C3.1 P4.1 R8.2 R14.1 R21.2
SCL: R35.2 TP7.1 U7.18 | length 1672.4
  Top Layer w10: R35.2 2100,1080 2290,890 2290,180 2330,140 2420,140 TP7.1 2480,250 2490,260 2660,260 2752.05,352.05 U7.18
SDA: R36.2 TP8.1 U7.17 | length 1440.4
  Top Layer w10: R36.2 2200,1010 2310,900 2310,330 2360,280 ; TP8.1 2360,280 ; U7.17 2732.36,362.36 2650,280 2360,280
SMPS_R\E\S\E\T\: C61.1 R37.2 U7.16 | length 100.4
  Top Layer w10: C61.1 1913.43,1159.02 R37.2
SWCLK: U7.59
SWDCLK: P5.3
SWDIO: P5.2 U7.60
SYNC: U8.8
Temp: R22.1 R29.1 TP17.1 U8.3 | length 412.3
  Top Layer w10: R22.1 v1(2540,2360)
  Bottom Layer w10: v1(2540,1980) v1(2540,2360)
"USB D+": R30.1 U7.46 | length 478.6
  Top Layer w10: U7.46 3168.27,748.27 v1(3180,760) ; v1(3180,700) 3250,700 3414.41,535.59 R30.1
  Bottom Layer w10: v1(3180,700) v1(3180,760)
"USB D-": R34.1 U7.45 | length 355
  Top Layer w10: U7.45 3261.42,728.58 3370,620 R34.1
Vbus_sense: C7.2 C52.1 R2.2 R7.1 TP11.1 U8.31 U8.40 | length 669.5
  Top Layer w10: R2.2 440,2410 C7.2@520.72,2410 ; C52.1 1779.28,1700.72 1799.28,1680.72 1799.28,1620.72 v1(1800,1620) 1862.83,1620 1871.42,1628.58 U8.31 ; v1(1800,1490) 1800,1460 1820,1440 1880,1440 1891.42,1451.42 U8.40
  Bottom Layer w10: v1(1800,1490) v1(1800,1620)
Vcells_sense: C3.2 C54.1 R3.2 R8.1 TP14.1 U8.33 U8.39 | length 543
  Top Layer w10: C54.1 1777.36,1589.21 v1(1830.79,1589.21) U8.33 ; v1(1830,1470) 1840,1460 1870,1460 1881.1,1471.1 U8.39 ; C3.2@3419.28,2410 3501.5,2410 3500,2408.5 R3.2
  Bottom Layer w10: v1(1830,1470) 1830,1588.43 v1(1830.79,1589.21)
pads on no net: J1.4 L2.3 U1.6 U7.1 U7.2 U7.3 U7.4 U7.5 U7.6 U7.9 U7.10 U7.11 U7.12 U7.13 U7.14 U7.15 U7.23 U7.24 U7.25 U7.26 U7.27 U7.28 U7.29 U7.30 U7.35 U7.36 U7.37 U7.38 U7.39 U7.40 U7.41 U7.42 U7.43 U7.44 U7.49 U7.50 U7.51 U7.55 U7.57 U7.58 U7.61 U7.62 U7.63 U7.64 U8.13 U8.14 U8.15 U8.16 U8.17 U8.18 U8.21 U8.22 U8.23 U8.24 U8.25

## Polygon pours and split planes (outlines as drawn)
Ccells on Top Layer "Ccells-top" (solid, pour order 83): 1660,2000 2430,2000 2430,2170 2648.5,2170 2648.5,2190 2648.51,2190 2580,2190 2580,2210 2649.52,2210 2649.52,2229.22 2650,2229.69 2650,2270 2500,2270 2510,2280 2510,2700 1660,2700
Rcells on Top Layer "Rcells-top" (solid, pour order 81): 3920,2360 3540,2360 3540,2440 3391.72,2440 3390,2441.72 3390,2700 3920,2700
+Vcells on Top Layer "Vcells-top" (solid, pour order 79): 2660,2190 2590.47,2190 2590.47,2210 2660,2210 2660,2700 2710,2700 3380,2700 3380,2300 3540,2300 3540,2350 3920,2350 3920,2000 2660,2000 2660,2150 2590.47,2150 2590.47,2170 2660,2170
Rbus on Top Layer "Rbus-top" (solid, pour order 77): 10,2440 10,2434.71 10,2360 400,2360 400,2440 548.28,2440 548.28,2698.28 550,2700 10,2700
+Vbus on Top Layer "Vbus-top" (solid, pour order 75): 400,2300 400,2350 10,2350 10,2000 1650,2000 1650,2700 560,2700 560,2300
GND on Bottom Layer "GND_bottom" (solid, shelved, pour order 72): 0,0 2362.2,0 2362.2,3149.61 0,3149.61
GND on Top Layer "GND_top" (solid, shelved, pour order 73): 0,0 2362.2,0 2362.2,3149.61 0,3149.61

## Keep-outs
Keep-Out Layer:
  the board outline again, w10

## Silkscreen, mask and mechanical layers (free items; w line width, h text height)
Top Overlay:
  the board outline again, w10
  text "UCD3138 V1.0" at 1500,40 h60
Drill Drawing:
  the board outline again, w10

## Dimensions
0,-39.37 to 3937.01,-78.74 on Mechanical 2
-39.37,0 to -39.37,3149.61 on Mechanical 2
